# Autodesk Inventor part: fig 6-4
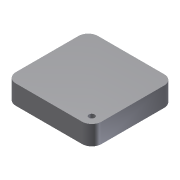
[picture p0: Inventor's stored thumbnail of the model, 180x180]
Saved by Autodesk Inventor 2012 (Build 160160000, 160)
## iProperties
Created: 2004-05
Part Number: fig 6-4
Document SubType Name: Modeling
Designer: CADCIM Technologies
Manufacturer: Standard
Standards Organization: Custom
Density: 1 g/cm^3
Material: Default
Author: CADCIM Technologies
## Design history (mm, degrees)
sketch "Sketch1"
  geometry: L1 (0, 0)-(44.293, 0); L2 (44.293, 0)-(44.293, 42.442); L3 (44.293, 42.442)-(0, 42.442); L4 (0, 42.442)-(0, 0)
  constraints: 8 end point, 2 parallel, 1 horizontal, 1 perpendicular
extrude "Extrusion1" new body sketch "Sketch1" distance "d0" = 10; taper "d1" = 0 deg
fillet "Fillet1" dims "d2" = 5
sketch "Sketch2"
  geometry: 1 further point
sketch "Sketch3"
  geometry: L1 (5, 42.442)-(39.293, 42.442) reference; L2 (0, 5)-(0, 37.442) reference; L3 (39.293, 0)-(5, 0) reference; L4 (44.293, 37.442)-(44.293, 5) reference; A1 r 5 centre (39.293, 37.442) between (44.293, 37.442) and (39.293, 42.442) reference; A2 r 5 centre (5, 37.442) between (5, 42.442) and (0, 37.442) reference; A3 r 5 centre (5, 5) between (0, 5) and (5, 0) reference; A4 r 5 centre (39.293, 5) between (39.293, 0) and (44.293, 5) reference; 1 further point
hole "Hole2" diameter "d15" = 3; stored, may be unused: countersink angle "d19" = 90 deg, drill point angle "d21" = 118 deg; dims "d13" = 10, "d14" = 10, "d16" = 6, "d17" = 4, "d18" = 2, "d20" = 8
body "Solid1"
